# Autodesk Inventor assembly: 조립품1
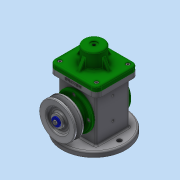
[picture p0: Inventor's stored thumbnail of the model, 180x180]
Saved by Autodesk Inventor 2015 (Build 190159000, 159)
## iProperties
Created: 2018-10
Part Number: 조립품1
Document SubType Name: Assembly
Designer: SCD-A02
Author: SCD-A02
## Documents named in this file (17)
- C:\Users\SCD-A02\Desktop\481007V1018\조립품1.iam
- C:\Users\SCD-A02\Desktop\481007V1018\본체.ipt
- C:\Users\SCD-A02\Desktop\481007V1018\편심축.ipt
- C:\Users\SCD-A02\Desktop\481007V1018\베어링 17 x 40 x 12.ipt
- C:\Users\SCD-A02\Desktop\481007V1018\오일 실 17 30 8.ipt
- C:\Users\SCD-A02\Desktop\481007V1018\키 4 x 4 x 12.ipt
- C:\Users\SCD-A02\Desktop\481007V1018\뒤커버.ipt
- C:\Users\SCD-A02\Desktop\481007V1018\앞커버.ipt
- C:\Users\SCD-A02\Desktop\481007V1018\슬라이더.ipt
- C:\Users\SCD-A02\Desktop\481007V1018\클레비스 핀 6 x 22.ipt
- 클레비스 핀 6 x 22.ipt
- C:\Users\SCD-A02\Desktop\481007V1018\링크.ipt
- C:\Users\SCD-A02\Desktop\481007V1018\덮개.ipt
- C:\Users\SCD-A02\Desktop\481007V1018\볼트 M4 x 8.ipt
- C:\Users\SCD-A02\Desktop\481007V1018\V-벨트풀리.ipt
- C:\Users\SCD-A02\Desktop\481007V1018\와셔 4x16.ipt
- C:\Users\SCD-A02\Desktop\481007V1018\볼트 M4 x 10.ipt
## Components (1 placed, 1 different names)
1. V-벨트풀리:1 — 각도:2
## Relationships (1: Angle 1)
- 각도:2 [Angle]: V-벨트풀리:1
